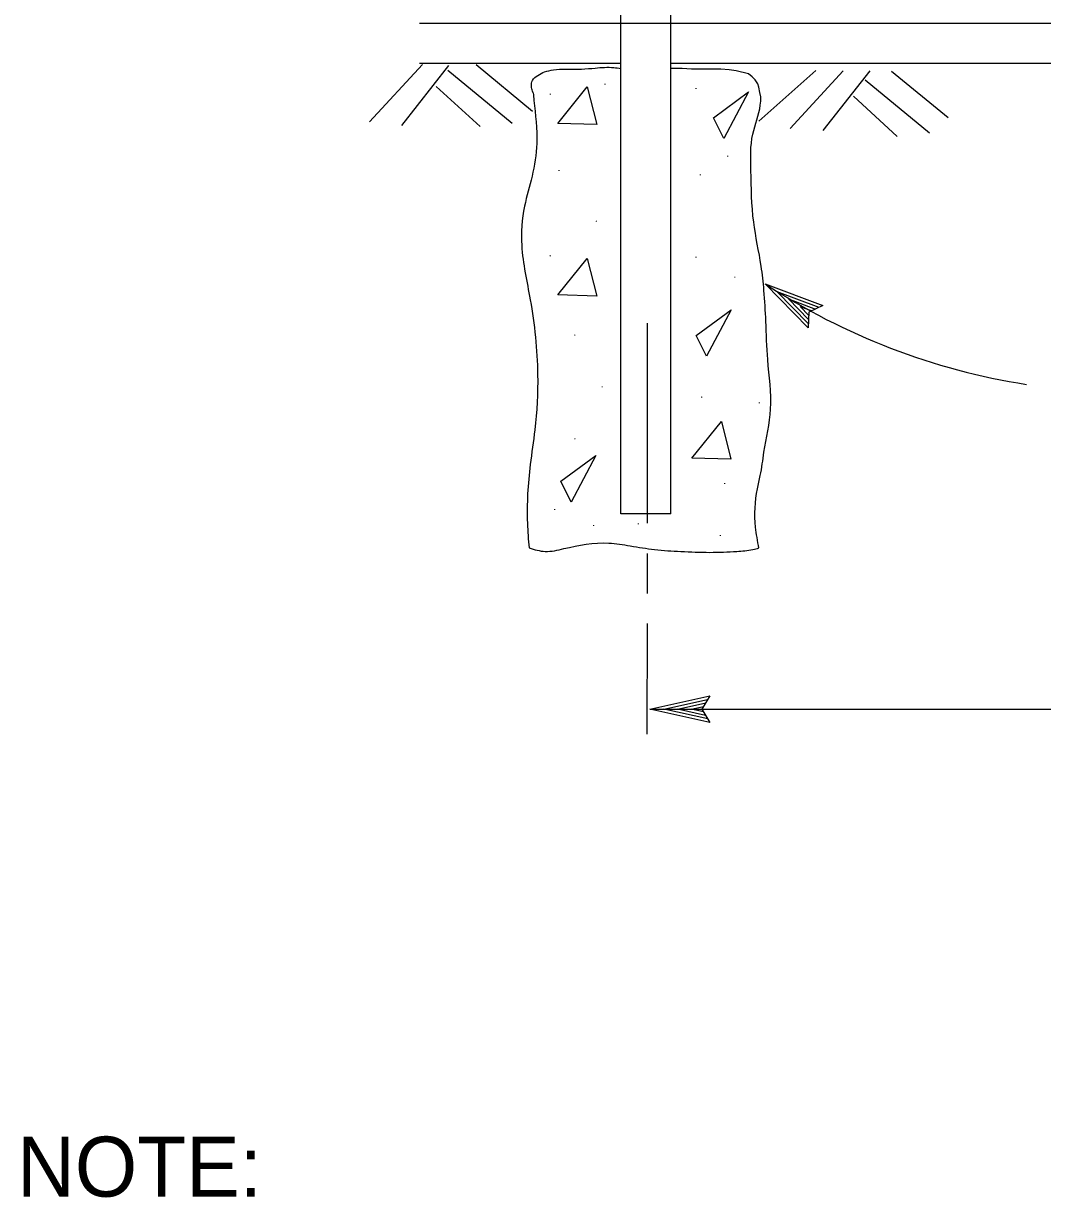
# Model space of a CAD drawing. Extents: x -123486 to -116575, y -107066 to -101122.
# Drawn here: x -118601.6 to -118499.6, y -102123.9 to -102006.5 of the extents above; entities that cross this region are included whole.
import ezdxf

# ---------------------------------------------------------------- set-up
doc = ezdxf.new("R2010")
doc.units = 0
for name, color, linetype in [('G-MARK', 7, 'Continuous'), ('G-TEXT', 7, 'Continuous'), ('Misc CnstDet(22)', 7, 'Continuous'), ('Nongeo Data(60)', 7, 'Continuous')]:
    doc.layers.add(name, color=color, linetype=linetype)

msp = doc.modelspace()

# ---------------------------------------------------------------- linework, layer by layer
at = {"layer": 'G-MARK'}
msp.add_line((-118538.9, -102075.04), (-118362.01, -102075.04), dxfattribs=at)
for points in [[(-118539.16, -102036.46), (-118539.18, -102056.46)], [(-118539.18, -102059.46), (-118539.18, -102063.46)], [(-118539.19, -102066.46), (-118539.2, -102077.54)]]:
    msp.add_lwpolyline(points, dxfattribs=at)
msp.add_arc((-118491.01, -101977.01), 66.35, 236.7837, 261.1414, dxfattribs=at)
at = {"layer": 'G-TEXT'}
for p, q in [((-118523.06, -102036.92), (-118527.36, -102032.52)), ((-118527.36, -102032.52), (-118527.36, -102032.52)), ((-118527.36, -102032.52), (-118521.6, -102034.68)), ((-118523.04, -102036.5), (-118526.2, -102033.28)), ((-118526.19, -102033.28), (-118521.99, -102034.85)), ((-118523.04, -102036.07), (-118525.04, -102034.03)), ((-118525.04, -102034.03), (-118522.33, -102035.05)), ((-118523, -102035.69), (-118523.88, -102034.78)), ((-118523.88, -102034.78), (-118522.72, -102035.22)), ((-118523, -102035.36), (-118523.06, -102036.92)), ((-118521.6, -102034.68), (-118523, -102035.36)), ((-118521.6, -102034.68), (-118521.6, -102034.68)), ((-118523.06, -102036.92), (-118523.06, -102036.92)), ((-118538.9, -102075.04), (-118532.9, -102073.71)), ((-118537.51, -102075.03), (-118533.14, -102074.07)), ((-118532.9, -102073.71), (-118533.7, -102075.04)), ((-118532.9, -102073.71), (-118532.9, -102073.71)), ((-118532.9, -102076.38), (-118538.9, -102075.04)), ((-118538.9, -102075.04), (-118538.9, -102075.04)), ((-118533.12, -102076.02), (-118537.52, -102075.04)), ((-118536.14, -102075.04), (-118533.31, -102074.41)), ((-118533.35, -102075.66), (-118536.14, -102075.04)), ((-118534.76, -102075.04), (-118533.55, -102074.77)), ((-118533.53, -102075.31), (-118534.76, -102075.04)), ((-118533.7, -102075.04), (-118532.9, -102076.38)), ((-118532.9, -102076.38), (-118532.9, -102076.38))]:
    msp.add_line(p, q, dxfattribs=at)
at = {"layer": 'Nongeo Data(60)'}
for p, q in [((-118541.8, -102055.5), (-118541.8, -101901.31)), ((-118536.8, -102055.5), (-118536.8, -101901.31)), ((-118541.8, -102055.5), (-118541.8, -101905.5)), ((-118535.15, -102006.5), (-118561.96, -102006.5)), ((-118359.8, -102006.5), (-118535.15, -102006.5)), ((-118561.64, -102010.57), (-118566.93, -102016.33)), ((-118559.03, -102010.68), (-118563.73, -102016.67)), ((-118541.8, -102010.5), (-118561.96, -102010.5)), ((-118556.28, -102010.6), (-118550.64, -102015.24)), ((-118364.8, -102010.5), (-118536.8, -102010.5)), ((-118559.1, -102011.14), (-118552.66, -102016.45)), ((-118535.68, -102010.99), (-118536.76, -102010.99)), ((-118534.75, -102011.04), (-118535.68, -102010.99)), ((-118533.62, -102011.04), (-118534.75, -102011.04)), ((-118531.8, -102011.04), (-118533.62, -102011.04)), ((-118530.96, -102011.13), (-118531.8, -102011.04)), ((-118530.28, -102011.23), (-118530.96, -102011.13)), ((-118529.05, -102011.53), (-118530.28, -102011.23)), ((-118528.66, -102011.82), (-118529.05, -102011.53)), ((-118528.36, -102012.12), (-118528.66, -102011.82)), ((-118522.32, -102011.18), (-118528.02, -102016.25)), ((-118519.58, -102011.22), (-118524.88, -102016.97)), ((-118516.91, -102011.22), (-118521.61, -102017.2)), ((-118514.72, -102011.24), (-118509.08, -102015.88)), ((-118560.28, -102012.79), (-118555.88, -102016.8)), ((-118528.12, -102012.51), (-118528.36, -102012.12)), ((-118528.02, -102012.85), (-118528.12, -102012.51)), ((-118527.92, -102013.39), (-118528.02, -102012.85)), ((-118517.38, -102012.11), (-118510.93, -102017.42)), ((-118527.8, -102013.83), (-118527.92, -102013.39)), ((-118518.55, -102013.76), (-118514.16, -102017.77)), ((-118536.8, -102055.5), (-118541.8, -102055.5))]:
    msp.add_line(p, q, dxfattribs=at)
for points in [[(-118544.21, -102016.58), (-118548.11, -102016.47), (-118545.16, -102012.81)], [(-118529.04, -102013.33), (-118531.51, -102017.99), (-118532.54, -102015.91)], [(-118544.21, -102033.74), (-118548.11, -102033.63), (-118545.16, -102029.97)], [(-118530.77, -102035.11), (-118533.24, -102039.76), (-118534.27, -102037.69)], [(-118530.81, -102050.04), (-118534.71, -102049.93), (-118531.75, -102046.27)], [(-118544.32, -102049.68), (-118546.79, -102054.33), (-118547.82, -102052.25)]]:
    msp.add_lwpolyline(points, close=True, dxfattribs=at)
for points in [[(-118550.57, -102013.43), (-118550.65, -102013.25), (-118550.75, -102012.76), (-118550.65, -102012.17), (-118550.11, -102011.67), (-118549.43, -102011.33), (-118548.54, -102011.13), (-118547.32, -102011.04), (-118545.74, -102011.04), (-118544.37, -102010.94), (-118542.5, -102010.89), (-118541.82, -102010.99)], [(-118550.57, -102013.43), (-118550.5, -102014.18), (-118550.22, -102018.48), (-118550.69, -102021.76), (-118551.44, -102024.75), (-118551.72, -102028.68), (-118550.87, -102034.1), (-118550.13, -102041.59), (-118550.41, -102047.11), (-118550.87, -102050.57), (-118551.15, -102056.46), (-118550.99, -102058.92)], [(-118527.99, -102058.92), (-118528.33, -102056.84), (-118528.14, -102053), (-118527.86, -102051.69), (-118527.49, -102049.35), (-118526.83, -102045.05), (-118527.11, -102040.09), (-118527.3, -102036.26), (-118527.49, -102033.17), (-118527.77, -102030.74), (-118528.52, -102026.34), (-118528.8, -102021.19), (-118528.61, -102017.55), (-118527.86, -102014.65), (-118527.8, -102013.83)], [(-118550.99, -102058.92), (-118549.38, -102059.27), (-118547.51, -102058.99), (-118543.02, -102058.43), (-118540.86, -102058.71), (-118538.43, -102059.08), (-118535.81, -102059.27), (-118532.91, -102059.36), (-118530.2, -102059.27), (-118528.61, -102059.08), (-118527.99, -102058.92)]]:
    msp.add_spline(points, degree=3, dxfattribs=at)

# ---------------------------------------------------------------- texts
at = {"layer": 'Misc CnstDet(22)'}
msp.add_text('NOTE:', height=6, dxfattribs=at).set_placement((-118602.21, -102123.78))
at = {"layer": 'Nongeo Data(60)'}
for p in [(-118543.44, -102012.39), (-118534.35, -102012.82), (-118548.92, -102013.4), (-118531.18, -102019.6), (-118548.05, -102021.04), (-118533.92, -102021.47), (-118544.3, -102026.09), (-118548.92, -102029.55), (-118534.35, -102029.69), (-118530.46, -102031.71), (-118546.46, -102037.48), (-118543.73, -102042.67), (-118533.78, -102043.68), (-118528.01, -102044.26), (-118546.46, -102047.86), (-118531.47, -102052.33), (-118548.48, -102054.93), (-118544.59, -102056.52), (-118540.12, -102056.37), (-118531.9, -102057.53)]:
    msp.add_text('.', height=0.8, rotation=266.9315, dxfattribs=at).set_placement(p)

doc.saveas('drawing.dxf')
